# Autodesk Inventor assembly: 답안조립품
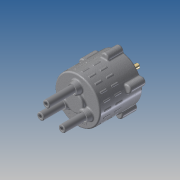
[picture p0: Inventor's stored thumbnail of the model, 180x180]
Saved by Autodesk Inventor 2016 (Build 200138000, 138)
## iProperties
Created: 2016-01
Part Number: 답안조립품
Document SubType Name: Assembly
Designer: Administrator
Author: Administrator
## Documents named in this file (14)
- C:\Users\Administrator\Desktop\새 폴더\360106V1035\답안조립품.iam
- C:\Users\Administrator\Desktop\새 폴더\360106V1035\본체.ipt
- C:\Users\Administrator\Desktop\새 폴더\360106V1035\M5x0.8x20.ipt
- C:\Users\Administrator\Desktop\새 폴더\360106V1035\멈춤링 10 x 1.ipt
- C:\Users\Administrator\Desktop\새 폴더\360106V1035\멈춤링 22 x 1.2.ipt
- C:\Users\Administrator\Desktop\새 폴더\360106V1035\메인 축.ipt
- C:\Users\Administrator\Desktop\새 폴더\360106V1035\베어링 NA 4900.ipt
- C:\Users\Administrator\Desktop\새 폴더\360106V1035\스프링1.ipt
- C:\Users\Administrator\Desktop\새 폴더\360106V1035\스프링2.ipt
- C:\Users\Administrator\Desktop\새 폴더\360106V1035\스프링3.ipt
- C:\Users\Administrator\Desktop\새 폴더\360106V1035\슬라이드 축.ipt
- C:\Users\Administrator\Desktop\새 폴더\360106V1035\오일실.ipt
- C:\Users\Administrator\Desktop\새 폴더\360106V1035\커버.ipt
- C:\Users\Administrator\Desktop\새 폴더\360106V1035\판캠.ipt
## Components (5 placed, 1 different names)
1. M5x0.8x20:1
2. M5x0.8x20:2
3. M5x0.8x20:3
4. M5x0.8x20:4
5. M5x0.8x20:5
